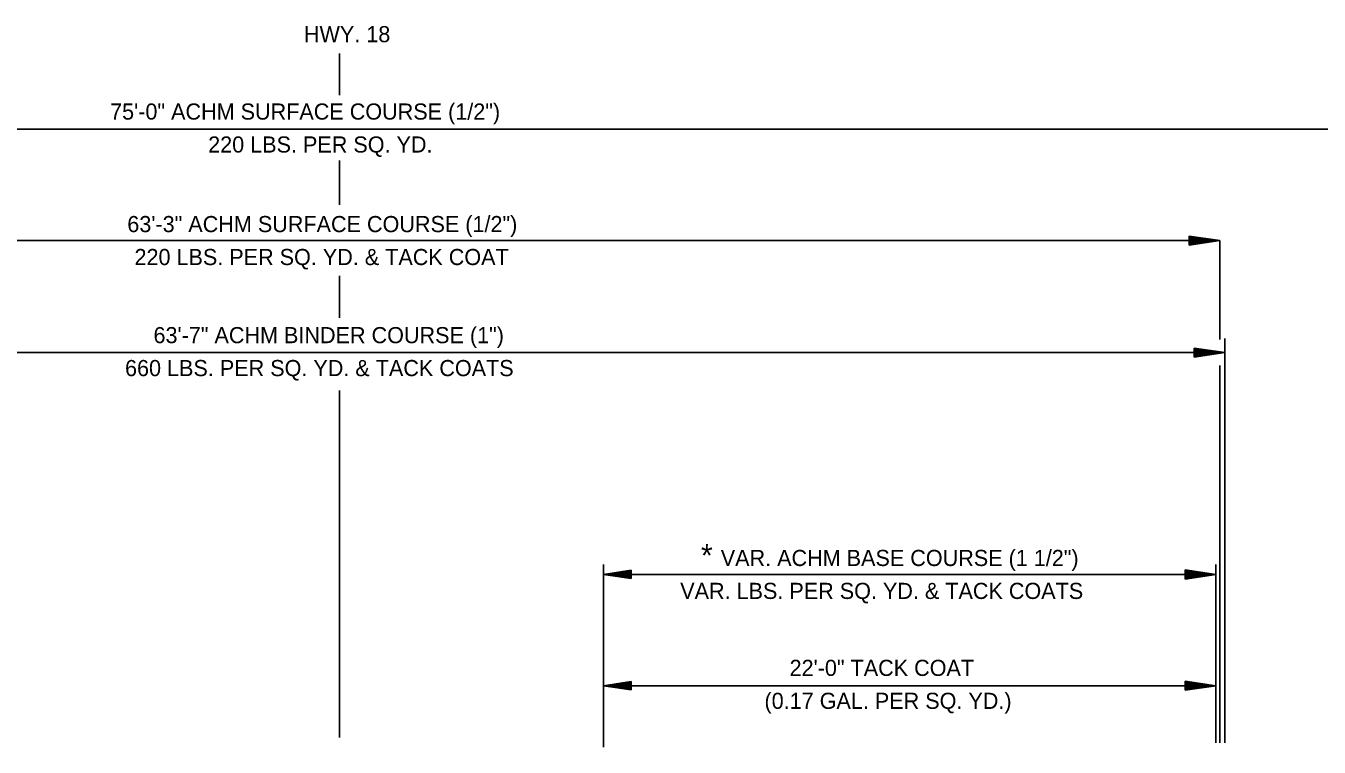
# Model space of a CAD drawing. Extents: x 634177 to 635904, y 289936 to 290970.
# Drawn here: x 635676.26 to 635722.74, y 290409.18 to 290435.11 of the extents above; entities that cross this region are included whole.
import ezdxf

# ---------------------------------------------------------------- set-up
doc = ezdxf.new("R2010")
doc.units = 0
for name, color, linetype in [('1', 7, 'Continuous'), ('7', 7, 'Continuous'), ('Default', 7, 'Continuous'), ('DIMS-TEXT', 7, 'Continuous')]:
    doc.layers.add(name, color=color, linetype=linetype)

msp = doc.modelspace()

# ---------------------------------------------------------------- linework, layer by layer
at = {"layer": '1'}
for p, q in [((635725.001, 290431.392), (635650.033, 290431.392)), ((635719.165, 290427.392), (635655.9, 290427.392)), ((635719.165, 290423.838), (635719.165, 290427.392)), ((635719.344, 290409.343), (635719.344, 290423.869)), ((635719.344, 290423.364), (635655.716, 290423.364)), ((635719.165, 290409.343), (635719.165, 290422.897)), ((635697.018, 290409.184), (635697.018, 290415.75)), ((635719.02, 290409.343), (635719.02, 290415.75)), ((635719.02, 290415.392), (635697.018, 290415.392)), ((635719.02, 290411.392), (635697.018, 290411.392))]:
    msp.add_line(p, q, dxfattribs=at)
at = {"layer": '7'}
for p, q in [((635718.065, 290427.557), (635719.165, 290427.392)), ((635718.065, 290427.557), (635718.065, 290427.227)), ((635718.065, 290427.529), (635718.981, 290427.392)), ((635718.065, 290427.501), (635718.792, 290427.392)), ((635718.065, 290427.474), (635718.609, 290427.392)), ((635718.065, 290427.445), (635718.423, 290427.392)), ((635718.065, 290427.417), (635718.239, 290427.392)), ((635718.065, 290427.227), (635719.165, 290427.392)), ((635718.065, 290427.338), (635718.423, 290427.392)), ((635718.065, 290427.282), (635718.792, 290427.392)), ((635718.065, 290427.254), (635718.981, 290427.392)), ((635718.065, 290427.31), (635718.609, 290427.392)), ((635718.065, 290427.366), (635718.239, 290427.392)), ((635718.244, 290423.529), (635719.344, 290423.364)), ((635718.244, 290423.529), (635718.244, 290423.199)), ((635718.244, 290423.501), (635719.16, 290423.364)), ((635718.244, 290423.473), (635718.971, 290423.364)), ((635718.244, 290423.446), (635718.788, 290423.364)), ((635718.244, 290423.417), (635718.602, 290423.364)), ((635718.244, 290423.389), (635718.418, 290423.364)), ((635718.244, 290423.199), (635719.344, 290423.364)), ((635718.244, 290423.31), (635718.602, 290423.364)), ((635718.244, 290423.254), (635718.971, 290423.364)), ((635718.244, 290423.226), (635719.16, 290423.364)), ((635718.244, 290423.282), (635718.788, 290423.364)), ((635718.244, 290423.338), (635718.418, 290423.364)), ((635698.017, 290415.543), (635697.017, 290415.393)), ((635698.017, 290415.243), (635697.017, 290415.393)), ((635698.017, 290415.518), (635697.184, 290415.393)), ((635698.017, 290415.268), (635697.184, 290415.393)), ((635698.017, 290415.492), (635697.356, 290415.393)), ((635698.017, 290415.293), (635697.356, 290415.393)), ((635698.017, 290415.467), (635697.522, 290415.393)), ((635698.017, 290415.318), (635697.522, 290415.393)), ((635698.017, 290415.442), (635697.692, 290415.393)), ((635698.017, 290415.344), (635697.692, 290415.393)), ((635698.017, 290415.416), (635697.859, 290415.393)), ((635698.017, 290415.369), (635697.859, 290415.393)), ((635698.017, 290415.243), (635698.017, 290415.543)), ((635717.92, 290415.557), (635719.02, 290415.392)), ((635717.92, 290415.557), (635717.92, 290415.227)), ((635717.92, 290415.529), (635718.836, 290415.392)), ((635717.92, 290415.501), (635718.647, 290415.392)), ((635717.92, 290415.474), (635718.464, 290415.392)), ((635717.92, 290415.445), (635718.278, 290415.392)), ((635717.92, 290415.417), (635718.094, 290415.392)), ((635717.92, 290415.227), (635719.02, 290415.392)), ((635717.92, 290415.338), (635718.278, 290415.392)), ((635717.92, 290415.282), (635718.647, 290415.392)), ((635717.92, 290415.254), (635718.836, 290415.392)), ((635717.92, 290415.31), (635718.464, 290415.392)), ((635717.92, 290415.366), (635718.094, 290415.392)), ((635698.017, 290411.543), (635697.017, 290411.393)), ((635698.017, 290411.518), (635697.184, 290411.393)), ((635698.017, 290411.492), (635697.356, 290411.393)), ((635698.017, 290411.467), (635697.522, 290411.393)), ((635698.017, 290411.442), (635697.692, 290411.393)), ((635698.017, 290411.416), (635697.859, 290411.393)), ((635698.017, 290411.243), (635698.017, 290411.543)), ((635717.92, 290411.557), (635719.02, 290411.392)), ((635717.92, 290411.557), (635717.92, 290411.227)), ((635717.92, 290411.529), (635718.836, 290411.392)), ((635717.92, 290411.501), (635718.647, 290411.392)), ((635717.92, 290411.474), (635718.464, 290411.392)), ((635717.92, 290411.445), (635718.278, 290411.392)), ((635717.92, 290411.417), (635718.094, 290411.392)), ((635698.017, 290411.243), (635697.017, 290411.393)), ((635698.017, 290411.268), (635697.184, 290411.393)), ((635698.017, 290411.293), (635697.356, 290411.393)), ((635698.017, 290411.318), (635697.522, 290411.393)), ((635698.017, 290411.344), (635697.692, 290411.393)), ((635698.017, 290411.369), (635697.859, 290411.393)), ((635717.92, 290411.227), (635719.02, 290411.392)), ((635717.92, 290411.338), (635718.278, 290411.392)), ((635717.92, 290411.282), (635718.647, 290411.392)), ((635717.92, 290411.254), (635718.836, 290411.392)), ((635717.92, 290411.31), (635718.464, 290411.392)), ((635717.92, 290411.366), (635718.094, 290411.392))]:
    msp.add_line(p, q, dxfattribs=at)
at = {"layer": 'Default'}
for p, q in [((635687.53, 290432.623), (635687.53, 290434.123)), ((635687.53, 290428.672), (635687.53, 290430.277)), ((635687.53, 290424.613), (635687.53, 290426.131)), ((635687.53, 290409.532), (635687.53, 290421.999))]:
    msp.add_line(p, q, dxfattribs=at)

# ---------------------------------------------------------------- texts
at = {"layer": '1'}
for s, height, p in [('75\'-0" ACHM SURFACE COURSE (1/2")', 0.58, (635679.288, 290431.741)), ('220 LBS. PER SQ. YD.', 0.58, (635682.813, 290430.557)), ('63\'-3" ACHM SURFACE COURSE (1/2")', 0.58, (635679.907, 290427.696)), ('220 LBS. PER SQ. YD. & TACK COAT', 0.58, (635680.165, 290426.512)), ('63\'-7" ACHM BINDER COURSE (1")', 0.58, (635680.848, 290423.704)), ('660 LBS. PER SQ. YD. & TACK COATS', 0.58, (635679.825, 290422.52)), ('*', 0.812, (635700.521, 290415.669)), ('VAR. ACHM BASE COURSE (1 1/2")', 0.58, (635701.233, 290415.694)), ('VAR. LBS. PER SQ. YD. & TACK COATS', 0.58, (635699.776, 290414.51)), ('22\'-0" TACK COAT', 0.58, (635703.706, 290411.743)), ('(0.17 GAL. PER SQ. YD.)', 0.58, (635702.804, 290410.559))]:
    msp.add_text(s, height=height, dxfattribs=at).set_placement(p)
at = {"layer": 'DIMS-TEXT'}
msp.add_text('HWY. 18', height=0.58, dxfattribs=at).set_placement((635686.254, 290434.523))

doc.saveas('drawing.dxf')
